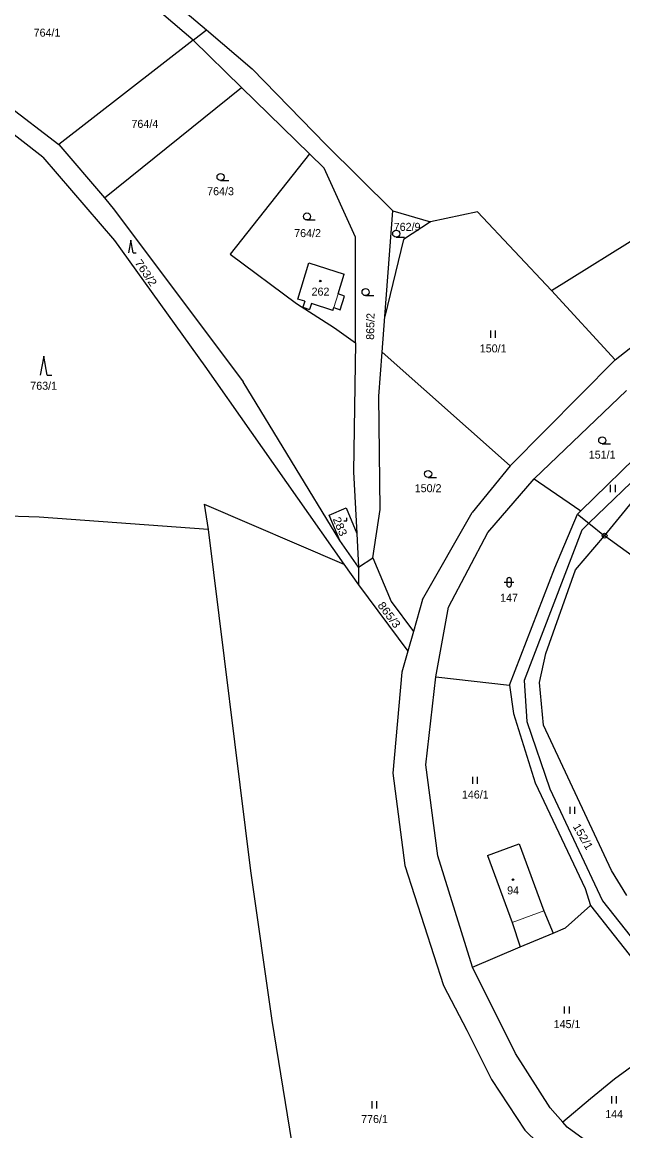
# Model space of a CAD drawing. Extents: x -739410 to -735662, y -942282 to -940043.
# Drawn here: x -737798.5 to -737671, y -940728 to -940492.6 of the extents above; entities that cross this region are included whole.
import ezdxf
from ezdxf.enums import TextEntityAlignment as Align

# ---------------------------------------------------------------- set-up
doc = ezdxf.new("R2010")
doc.units = 0
doc.header["$LTSCALE"] = 0.68
for name, color, linetype, lineweight in [('1', 7, 'Continuous', 25), ('3', 7, 'Continuous', 25), ('4', 7, 'Continuous', 13), ('5', 7, 'Continuous', 25), ('8', 7, 'Continuous', 25)]:
    doc.layers.add(name, color=color, linetype=linetype, lineweight=lineweight)
doc.layers.add('2', color=7, linetype='Continuous')

msp = doc.modelspace()

# ---------------------------------------------------------------- linework, layer by layer
at = {"layer": '1'}
for p, q in [((-737762.24, -940496.42), (-737793.91, -940469.06)), ((-737779.03, -940477.55), (-737759.41, -940494.23)), ((-737762.24, -940496.42), (-737759.41, -940494.23)), ((-737759.41, -940494.23), (-737749.72, -940502.47)), ((-737794.14, -940521.27), (-737825.64, -940496.73)), ((-737762.24, -940496.42), (-737790.75, -940518.52)), ((-737751.96, -940506.47), (-737762.24, -940496.42)), ((-737749.72, -940502.47), (-737734.05, -940518.57)), ((-737781.07, -940529.88), (-737751.96, -940506.47)), ((-737737.55, -940520.55), (-737751.96, -940506.47)), ((-737790.75, -940518.52), (-737781.07, -940529.88)), ((-737719.83, -940532.62), (-737734.05, -940518.57)), ((-737794.14, -940521.27), (-737778.92, -940538.96)), ((-737737.55, -940520.55), (-737754.35, -940541.86)), ((-737734.39, -940523.6), (-737737.55, -940520.55)), ((-737727.74, -940538.26), (-737734.39, -940523.6)), ((-737686.19, -940549.57), (-737648.64, -940526.17)), ((-737781.07, -940529.88), (-737778.92, -940532.5)), ((-737778.92, -940532.5), (-737751.64, -940568.92)), ((-737721.55, -940555.1), (-737719.83, -940532.62)), ((-737719.83, -940532.62), (-737711.82, -940535.01)), ((-737701.89, -940532.83), (-737711.82, -940535.01)), ((-737686.19, -940549.57), (-737701.89, -940532.83)), ((-737711.82, -940535.01), (-737717.59, -940538.7)), ((-737727.74, -940560.69), (-737727.74, -940538.26)), ((-737717.59, -940538.7), (-737721.55, -940555.1)), ((-737778.92, -940538.96), (-737759.76, -940565.66)), ((-737740.04, -940551.37), (-737737.69, -940543.68)), ((-737737.69, -940543.68), (-737730.2, -940546.07)), ((-737731.44, -940550.29), (-737730.2, -940546.07)), ((-737730.08, -940550.73), (-737731.44, -940550.29)), ((-737672.65, -940564.31), (-737686.19, -940549.57)), ((-737738.51, -940551.84), (-737740.04, -940551.37)), ((-737738.51, -940551.84), (-737738.93, -940553.13)), ((-737737.12, -940552.31), (-737737.5, -940553.57)), ((-737732.57, -940553.77), (-737737.12, -940552.31)), ((-737731.03, -940553.68), (-737730.08, -940550.73)), ((-737672.65, -940564.31), (-737655.92, -940550.97)), ((-737738.93, -940553.13), (-737737.5, -940553.57)), ((-737732.57, -940553.77), (-737732.38, -940553.19)), ((-737732.38, -940553.19), (-737731.03, -940553.68)), ((-737722.13, -940562.65), (-737721.55, -940555.1)), ((-737732.25, -940557.5), (-737727.74, -940560.69)), ((-737727.74, -940560.69), (-737728.19, -940588.04)), ((-737722.85, -940571.99), (-737722.13, -940562.65)), ((-737722.13, -940562.65), (-737694.96, -940586.79)), ((-737694.96, -940586.79), (-737672.65, -940564.31)), ((-737759.76, -940565.66), (-737730.26, -940607.67)), ((-737731.06, -940602.67), (-737751.64, -940568.92)), ((-737645.19, -940567.1), (-737678.21, -940598.98)), ((-737689.83, -940589.57), (-737670.2, -940570.81)), ((-737722.53, -940596.06), (-737722.85, -940571.99)), ((-737679.94, -940596.35), (-737661.75, -940578.53)), ((-737728.19, -940588.04), (-737727.47, -940601.15)), ((-737694.96, -940586.79), (-737703.02, -940596.72)), ((-737674.87, -940601.62), (-737663.18, -940587.21)), ((-737699.69, -940600.95), (-737689.83, -940589.57)), ((-737689.83, -940589.57), (-737688.91, -940590.21)), ((-737688.91, -940590.21), (-737679.94, -940596.35)), ((-737759.87, -940594.92), (-737759.08, -940600.31)), ((-737759.87, -940594.92), (-737730.26, -940607.67)), ((-737794.93, -940597.71), (-737811.98, -940597.17)), ((-737733.36, -940597.24), (-737729.77, -940595.72)), ((-737731.06, -940602.67), (-737733.36, -940597.24)), ((-737729.77, -940595.72), (-737727.47, -940601.15)), ((-737724.06, -940606.31), (-737722.53, -940596.06)), ((-737713.54, -940615.16), (-737703.02, -940596.72)), ((-737685.43, -940608.47), (-737680.65, -940597.05)), ((-737680.65, -940597.05), (-737679.94, -940596.35)), ((-737680.65, -940597.05), (-737678.21, -940598.98)), ((-737759.08, -940600.31), (-737794.93, -940597.71)), ((-737678.21, -940598.98), (-737679.71, -940600.42)), ((-737678.21, -940598.98), (-737674.87, -940601.62)), ((-737759.08, -940600.31), (-737750.06, -940672.77)), ((-737727.47, -940601.15), (-737727.13, -940608.33)), ((-737708, -940616.81), (-737699.69, -940600.95)), ((-737679.71, -940600.42), (-737691.96, -940632.4)), ((-737681.07, -940608.84), (-737674.87, -940601.62)), ((-737635.43, -940630.52), (-737674.87, -940601.62)), ((-737727.13, -940608.33), (-737731.06, -940602.67)), ((-737727.13, -940608.33), (-737724.06, -940606.31)), ((-737730.26, -940607.67), (-737727.16, -940612.09)), ((-737727.13, -940608.33), (-737727.16, -940612.09)), ((-737695.04, -940633.39), (-737685.43, -940608.47)), ((-737687.33, -940626.67), (-737681.07, -940608.84)), ((-737727.16, -940612.09), (-737716.65, -940626.11)), ((-737713.54, -940615.16), (-737715.47, -940621.97)), ((-737710.68, -940631.62), (-737708, -940616.81)), ((-737715.47, -940621.97), (-737716.65, -940626.11)), ((-737716.65, -940626.11), (-737717.93, -940630.6)), ((-737688.69, -940632.79), (-737687.33, -940626.67)), ((-737717.93, -940630.6), (-737719.85, -940652.03)), ((-737712.86, -940650.26), (-737710.68, -940631.62)), ((-737710.68, -940631.62), (-737695.04, -940633.39)), ((-737691.96, -940632.4), (-737691.41, -940641.11)), ((-737687.87, -940641.85), (-737688.69, -940632.79)), ((-737695.04, -940633.39), (-737694.22, -940639.37)), ((-737694.22, -940639.37), (-737689.6, -940654.07)), ((-737691.41, -940641.11), (-737686.51, -940655.37)), ((-737673.45, -940672.74), (-737687.87, -940641.85)), ((-737710.27, -940669.58), (-737712.86, -940650.26)), ((-737719.85, -940652.03), (-737717.26, -940671.65)), ((-737689.6, -940654.07), (-737678.99, -940676.52)), ((-737686.51, -940655.37), (-737675.36, -940679.19)), ((-737699.73, -940669.5), (-737692.99, -940667.02)), ((-737692.99, -940667.02), (-737687.77, -940681.25)), ((-737702.93, -940693.21), (-737710.27, -940669.58)), ((-737699.73, -940669.5), (-737694.51, -940683.73)), ((-737750.06, -940672.77), (-737745.55, -940704.54)), ((-737717.26, -940671.65), (-737709.08, -940697.16)), ((-737670.19, -940678.03), (-737673.45, -940672.74)), ((-737678.99, -940676.52), (-737677.9, -940680.14)), ((-737675.36, -940679.19), (-737655.5, -940704.3)), ((-737687.77, -940681.25), (-737685.81, -940686.01)), ((-737683.2, -940684.91), (-737677.9, -940680.14)), ((-737677.9, -940680.14), (-737657.7, -940705.77)), ((-737694.51, -940683.73), (-737692.79, -940688.95)), ((-737692.79, -940688.95), (-737685.81, -940686.01)), ((-737685.81, -940686.01), (-737683.2, -940684.91)), ((-737702.93, -940693.21), (-737692.79, -940688.95)), ((-737693.81, -940711.58), (-737702.93, -940693.21)), ((-737709.08, -940697.16), (-737704.16, -940706.62)), ((-737745.55, -940704.54), (-737732.8, -940782.36)), ((-737704.16, -940706.62), (-737698.92, -940717.1)), ((-737663.12, -940709.92), (-737672.8, -940717.05)), ((-737686.47, -940723.14), (-737693.81, -940711.58)), ((-737698.92, -940717.1), (-737691.83, -940727.87)), ((-737672.8, -940717.05), (-737677.9, -940721.2)), ((-737677.9, -940721.2), (-737683.76, -940726.16)), ((-737683.76, -940726.16), (-737686.47, -940723.14)), ((-737682.8, -940727.23), (-737683.76, -940726.16)), ((-737691.83, -940727.87), (-737680.14, -940739.12)), ((-737673.1, -940734.3), (-737682.8, -940727.23))]:
    msp.add_line(p, q, dxfattribs=at)
for points in [[(-737825.64, -940496.73), (-737824.58, -940492.63), (-737790.75, -940518.52)], [(-737754.35, -940541.86), (-737740.28, -940552.34), (-737732.25, -940557.5)], [(-737724.06, -940606.31), (-737720.19, -940615.61), (-737715.47, -940621.97)]]:
    msp.add_lwpolyline(points, dxfattribs=at)
at = {"layer": '3'}
for p, q in [((-737756.413, -940526.2), (-737754.663, -940526.2)), ((-737738.073, -940534.58), (-737736.323, -940534.58)), ((-737719.123, -940538.24), (-737717.373, -940538.24)), ((-737774.978, -940541.58), (-737774.31, -940541.58)), ((-737725.633, -940550.65), (-737723.883, -940550.65)), ((-737699.051, -940559.58), (-737699.051, -940558.08)), ((-737698.05, -940559.58), (-737698.05, -940558.08)), ((-737793.22, -940567.51), (-737792.224, -940567.51)), ((-737675.393, -940582.14), (-737673.643, -940582.14)), ((-737712.343, -940589.26), (-737710.593, -940589.26)), ((-737673.601, -940592.35), (-737673.601, -940590.85)), ((-737672.6, -940592.35), (-737672.6, -940590.85)), ((-737696.171, -940611.521), (-737694.169, -940611.521)), ((-737695.671, -940611.021), (-737695.671, -940612.022)), ((-737694.669, -940612.022), (-737694.669, -940611.021)), ((-737702.851, -940654.31), (-737702.851, -940652.81)), ((-737701.85, -940654.31), (-737701.85, -940652.81)), ((-737682.201, -940660.71), (-737682.201, -940659.21)), ((-737681.2, -940660.71), (-737681.2, -940659.21)), ((-737683.371, -940703.06), (-737683.371, -940701.56)), ((-737682.37, -940703.06), (-737682.37, -940701.56)), ((-737724.241, -940723.22), (-737724.241, -940721.72)), ((-737723.24, -940723.22), (-737723.24, -940721.72)), ((-737673.371, -940722.17), (-737673.371, -940720.67)), ((-737672.37, -940722.17), (-737672.37, -940720.67))]:
    msp.add_line(p, q, dxfattribs=at)
for points in [[(-737774.978, -940541.58), (-737775.48, -940538.9), (-737775.982, -940541.58)], [(-737793.22, -940567.51), (-737793.97, -940563.51), (-737794.72, -940567.51)], [(-737730.251, -940598.49), (-737729.58, -940598.49), (-737729.58, -940597.82)]]:
    msp.add_lwpolyline(points, dxfattribs=at)
for centre in [(-737756.4129, -940525.4498), (-737738.0729, -940533.8298), (-737719.1229, -940537.4898), (-737725.6329, -940549.8998), (-737675.3929, -940581.3898), (-737712.3429, -940588.5098)]:
    msp.add_circle(centre, 0.75, dxfattribs=at)
for centre, start, end in [((-737695.17, -940611.0209), 0, 180), ((-737695.17, -940612.0209), 180, 359.98789)]:
    msp.add_arc(centre, 0.5, start, end, dxfattribs=at)
at = {"layer": '4'}
for p, q in [((-737732.38, -940553.19), (-737731.44, -940550.29)), ((-737694.51, -940683.73), (-737687.77, -940681.25))]:
    msp.add_line(p, q, dxfattribs=at)
at = {"layer": '5'}
for centre in [(-737735.2368, -940547.5492), (-737694.3168, -940674.6592)]:
    msp.add_circle(centre, 0.175, dxfattribs=at)
at = {"layer": '8'}
for radius in [0.5, 0.0303]:
    msp.add_circle((-737674.87, -940601.6199), radius, dxfattribs=at)

# ---------------------------------------------------------------- texts
at = {"layer": '2'}
for s, p in [('764/1', (-737793.26, -940495.655)), ('764/4', (-737772.49, -940515.025)), ('764/3', (-737756.42, -940529.325)), ('762/9', (-737716.81, -940536.895)), ('764/2', (-737737.94, -940538.225)), ('262', (-737735.199, -940550.645)), ('150/1', (-737698.54, -940562.705)), ('763/1', (-737793.97, -940570.635)), ('151/1', (-737675.4, -940585.265)), ('150/2', (-737712.35, -940592.385)), ('147', (-737695.169, -940615.645)), ('146/1', (-737702.34, -940657.435)), ('94', (-737694.309, -940677.785)), ('145/1', (-737682.86, -940706.185)), ('776/1', (-737723.73, -940726.345)), ('144', (-737672.859, -940725.295))]:
    msp.add_text(s, height=1.7, dxfattribs=at).set_placement(p, align=Align.CENTER)
for s, rotation, width, p in [('763/2', 304, 1.1, (-737772.9589, -940546.2592)), ('283', 293, 1.1, (-737731.8293, -940599.9949)), ('865/3', 307, 1.1, (-737721.2929, -940618.9455)), ('152/1', 300, 1.05, (-737680.203, -940665.9285))]:
    msp.add_text(s, height=1.7, rotation=rotation, dxfattribs=dict(at, width=width)).set_placement(p, align=Align.CENTER)
msp.add_text('865/2', height=1.7, rotation=89, dxfattribs=at).set_placement((-737723.7744, -940557.1998), align=Align.CENTER)

doc.saveas('drawing.dxf')
